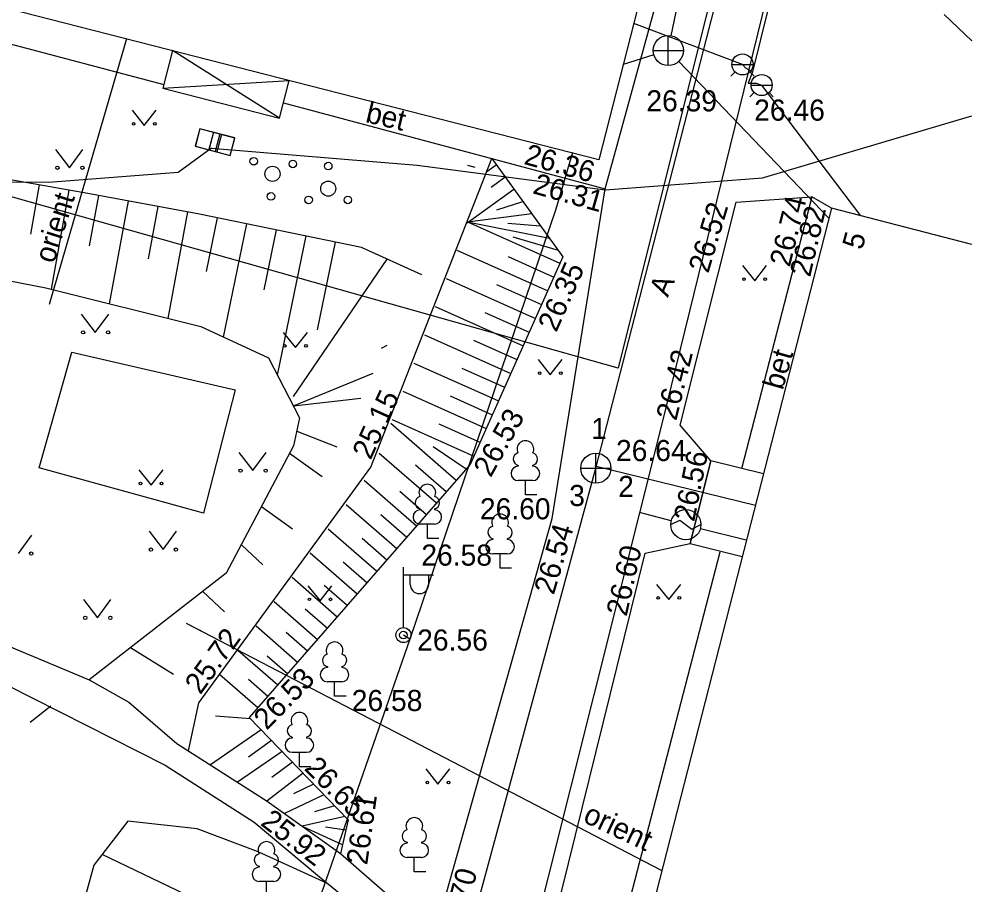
# Model space of a CAD drawing. Extents: x 714391 to 714584, y 6589993 to 6590151.
# Drawn here: x 714552.34 to 714583.92, y 6590039.38 to 6590068.08 of the extents above; entities that cross this region are included whole.
import ezdxf

# ---------------------------------------------------------------- set-up
doc = ezdxf.new("R2010")
doc.units = 0
for name, color, linetype in [('HALJASTUS', 7, 'Continuous'), ('HOONE', 7, 'Continuous'), ('HOONEDET', 7, 'Continuous'), ('KKAEV', 7, 'Continuous'), ('KORGUS', 7, 'Continuous'), ('KTRASS', 7, 'Continuous'), ('MPKAABEL', 7, 'Continuous'), ('POST', 7, 'Continuous'), ('PUU', 7, 'Continuous'), ('RAJATIS', 7, 'Continuous'), ('RELJEEF', 7, 'Continuous'), ('SITRASS', 7, 'Continuous'), ('SKTRASS', 7, 'Continuous'), ('TEE', 7, 'Continuous'), ('TORU NR', 7, 'Continuous'), ('VKAEV', 7, 'Continuous'), ('VTRASS', 7, 'Continuous'), ('Слой 1', 7, 'Continuous')]:
    doc.layers.add(name, color=color, linetype=linetype)

msp = doc.modelspace()

# ---------------------------------------------------------------- linework, layer by layer
at = {"layer": 'HALJASTUS'}
for p, q in [((714556.086, 6590065.052), (714556.491, 6590064.547)), ((714556.491, 6590064.547), (714556.886, 6590065.052)), ((714553.55, 6590063.754), (714554.013, 6590063.147)), ((714554.013, 6590063.147), (714554.459, 6590063.754)), ((714576.315, 6590059.904), (714576.72, 6590059.399)), ((714576.72, 6590059.399), (714577.115, 6590059.904)), ((714554.401, 6590058.3), (714554.864, 6590057.693)), ((714554.864, 6590057.693), (714555.31, 6590058.3)), ((714561.098, 6590057.692), (714561.503, 6590057.187)), ((714561.503, 6590057.187), (714561.898, 6590057.692)), ((714569.542, 6590056.789), (714569.947, 6590056.284)), ((714569.947, 6590056.284), (714570.342, 6590056.789)), ((714559.622, 6590053.715), (714560.085, 6590053.108)), ((714560.085, 6590053.108), (714560.531, 6590053.715)), ((714556.312, 6590053.131), (714556.717, 6590052.626)), ((714556.717, 6590052.626), (714557.112, 6590053.131)), ((714552.318, 6590050.359), (714552.764, 6590050.966)), ((714556.648, 6590051.099), (714557.111, 6590050.492)), ((714557.111, 6590050.492), (714557.557, 6590051.099)), ((714561.911, 6590049.293), (714562.316, 6590048.788)), ((714562.316, 6590048.788), (714562.711, 6590049.293)), ((714573.47, 6590049.338), (714573.875, 6590048.833)), ((714573.875, 6590048.833), (714574.27, 6590049.338)), ((714554.474, 6590048.837), (714554.937, 6590048.23)), ((714554.937, 6590048.23), (714555.383, 6590048.837)), ((714565.819, 6590043.22), (714566.224, 6590042.715)), ((714566.224, 6590042.715), (714566.619, 6590043.22))]:
    msp.add_line(p, q, dxfattribs=at)
for centre, radius in [((714556.138, 6590064.602), 0.0428), ((714556.838, 6590064.602), 0.0452), ((714553.612, 6590063.147), 0.055), ((714554.441, 6590063.147), 0.055), ((714576.367, 6590059.454), 0.0428), ((714577.067, 6590059.454), 0.0452), ((714554.463, 6590057.693), 0.055), ((714555.292, 6590057.693), 0.055), ((714561.15, 6590057.242), 0.0428), ((714561.85, 6590057.242), 0.0452), ((714569.594, 6590056.339), 0.0428), ((714570.294, 6590056.339), 0.0452), ((714559.684, 6590053.108), 0.055), ((714560.513, 6590053.108), 0.055), ((714556.364, 6590052.681), 0.0428), ((714557.064, 6590052.681), 0.0452), ((714552.746, 6590050.359), 0.055), ((714556.71, 6590050.492), 0.055), ((714557.539, 6590050.492), 0.055), ((714561.963, 6590048.843), 0.0428), ((714562.663, 6590048.843), 0.0452), ((714573.522, 6590048.889), 0.0428), ((714574.222, 6590048.889), 0.0452), ((714554.536, 6590048.23), 0.055), ((714555.365, 6590048.23), 0.055), ((714565.871, 6590042.77), 0.0428), ((714566.571, 6590042.77), 0.0452)]:
    msp.add_circle(centre, radius, dxfattribs=at)
at = {"layer": 'HOONE'}
for p, q in [((714573.956, 6590051.446), (714572.902, 6590051.725)), ((714573.939, 6590051.318), (714574.239, 6590051.468)), ((714574.239, 6590051.468), (714574.639, 6590051.168)), ((714574.639, 6590051.168), (714574.939, 6590051.318)), ((714574.924, 6590051.196), (714576.435, 6590050.818))]:
    msp.add_line(p, q, dxfattribs=at)
for points in [[(714571.553, 6590063.416), (714531.849, 6590073.579), (714534.607, 6590084.082)], [(714534.607, 6590084.082), (714574.255, 6590073.951), (714571.553, 6590063.416)], [(714564.262, 6590078.768), (714578.616, 6590074.926), (714573.649, 6590054.703), (714566.105, 6590024.628), (714563.31, 6590014.121), (714563.349, 6590014.272), (714562.951, 6590012.774), (714559.846, 6590001.436), (714579.323, 6589995.303), (714578.688, 6589992.711)], [(714557.429, 6590067.031), (714557.109, 6590065.783), (714560.975, 6590064.794), (714561.294, 6590066.042)], [(714583.92, 6590060.605), (714579.267, 6590061.805), (714569.151, 6590022.283), (714566.669, 6590012.701), (714564.179, 6590002.982), (714564.176, 6590002.972), (714574.684, 6590000.28), (714583.92, 6590036.33)], [(714577.009, 6590053.004), (714575.263, 6590053.437), (714574.585, 6590050.689), (714576.306, 6590050.266)]]:
    msp.add_lwpolyline(points, dxfattribs=at)
msp.add_circle((714574.439, 6590051.318), 0.5, dxfattribs=at)
at = {"layer": 'HOONEDET'}
for p, q in [((714560.975, 6590064.794), (714557.429, 6590067.031)), ((714557.109, 6590065.783), (714561.294, 6590066.042)), ((714574.585, 6590050.689), (714575.263, 6590053.437))]:
    msp.add_line(p, q, dxfattribs=at)
at = {"layer": 'KKAEV'}
for p, q in [((714573.858, 6590066.535), (714573.858, 6590067.535)), ((714573.358, 6590067.035), (714574.358, 6590067.035)), ((714571.457, 6590052.69), (714571.457, 6590053.69)), ((714570.957, 6590053.19), (714571.957, 6590053.19))]:
    msp.add_line(p, q, dxfattribs=at)
for centre in [(714573.858, 6590067.035), (714571.457, 6590053.19)]:
    msp.add_circle(centre, 0.5, dxfattribs=at)
at = {"layer": 'KTRASS'}
for p, q in [((714571.457, 6590053.19), (714577.77, 6590077.701)), ((714573.381, 6590066.887), (714572.362, 6590066.57)), ((714566.306, 6590034.202), (714571.457, 6590053.19)), ((714571.425, 6590053.27), (714576.748, 6590051.963))]:
    msp.add_line(p, q, dxfattribs=at)
at = {"layer": 'MPKAABEL'}
for points in [[(714558.719, 6590063.793), (714565.529, 6590063.23), (714571.775, 6590062.412), (714576.976, 6590062.818), (714583.92, 6590064.869)], [(714558.719, 6590063.793), (714557.614, 6590062.993), (714553.32, 6590062.662), (714527.694, 6590062.802), (714519.691, 6590062.433), (714508.979, 6590063.853), (714473.93, 6590041.599)], [(714570.681, 6590063.65), (714570.135, 6590061.772), (714565.296, 6590047.518), (714565.078, 6590047.659)], [(714565.296, 6590047.518), (714562.179, 6590038.578), (714559.533, 6590030.225), (714556.889, 6590017.808), (714556.781, 6590017.088), (714556.359, 6590014.294), (714555.801, 6590010.589), (714547.733, 6590015.896), (714531.176, 6590026.61), (714500.538, 6590019.577)]]:
    msp.add_lwpolyline(points, dxfattribs=at)
at = {"layer": 'POST'}
for p, q in [((714558.336, 6590064.443), (714558.181, 6590063.867)), ((714558.336, 6590064.443), (714558.182, 6590063.867)), ((714559.49, 6590064.136), (714558.336, 6590064.443)), ((714559.489, 6590064.133), (714558.336, 6590064.443)), ((714558.781, 6590064.323), (714558.626, 6590063.747)), ((714558.782, 6590064.325), (714558.628, 6590063.748)), ((714558.992, 6590064.269), (714558.838, 6590063.692)), ((714559.044, 6590064.253), (714558.889, 6590063.677)), ((714559.334, 6590063.557), (714559.489, 6590064.133)), ((714559.337, 6590063.559), (714559.49, 6590064.136)), ((714558.181, 6590063.867), (714559.334, 6590063.557)), ((714558.182, 6590063.867), (714559.337, 6590063.559)), ((714565.078, 6590047.909), (714565.078, 6590049.909)), ((714565.078, 6590049.659), (714566.078, 6590049.659)), ((714565.305, 6590049.338), (714565.305, 6590049.659)), ((714565.917, 6590049.338), (714565.917, 6590049.659)), ((714565.078, 6590047.659), (714565.078, 6590047.659))]:
    msp.add_line(p, q, dxfattribs=at)
for radius in [0.25, 0.127]:
    msp.add_circle((714565.078, 6590047.659), radius, dxfattribs=at)
msp.add_arc((714565.611, 6590049.338), 0.306, 180, 0, dxfattribs=at)
at = {"layer": 'PUU'}
for p, q in [((714568.881, 6590053.284), (714568.881, 6590053.254)), ((714569.361, 6590053.284), (714569.361, 6590053.254)), ((714569.361, 6590052.779), (714568.881, 6590052.779)), ((714569.121, 6590052.304), (714569.121, 6590052.779)), ((714569.501, 6590052.304), (714569.121, 6590052.304)), ((714565.631, 6590051.839), (714565.631, 6590051.809)), ((714566.111, 6590051.839), (714566.111, 6590051.809)), ((714566.111, 6590051.334), (714565.631, 6590051.334)), ((714565.871, 6590050.859), (714565.871, 6590051.334)), ((714566.251, 6590050.859), (714565.871, 6590050.859)), ((714568.042, 6590050.852), (714568.042, 6590050.822)), ((714568.522, 6590050.852), (714568.522, 6590050.822)), ((714568.522, 6590050.347), (714568.042, 6590050.347)), ((714568.282, 6590049.872), (714568.282, 6590050.347)), ((714568.662, 6590049.872), (714568.282, 6590049.872)), ((714562.557, 6590046.612), (714562.557, 6590046.582)), ((714563.037, 6590046.612), (714563.037, 6590046.582)), ((714563.037, 6590046.107), (714562.557, 6590046.107)), ((714562.797, 6590045.632), (714562.797, 6590046.107)), ((714563.177, 6590045.632), (714562.797, 6590045.632)), ((714561.391, 6590044.276), (714561.391, 6590044.246)), ((714561.871, 6590044.276), (714561.871, 6590044.246)), ((714561.871, 6590043.771), (714561.391, 6590043.771)), ((714561.631, 6590043.296), (714561.631, 6590043.771)), ((714562.011, 6590043.296), (714561.631, 6590043.296)), ((714565.2, 6590040.79), (714565.2, 6590040.76)), ((714565.68, 6590040.79), (714565.68, 6590040.76)), ((714565.68, 6590040.285), (714565.2, 6590040.285)), ((714565.44, 6590039.81), (714565.44, 6590040.285)), ((714560.299, 6590039.995), (714560.299, 6590039.965)), ((714560.779, 6590039.995), (714560.779, 6590039.965)), ((714565.82, 6590039.81), (714565.44, 6590039.81)), ((714560.779, 6590039.49), (714560.299, 6590039.49)), ((714560.539, 6590039.015), (714560.539, 6590039.49))]:
    msp.add_line(p, q, dxfattribs=at)
for centre, radius in [((714560.118, 6590063.365), 0.125), ((714561.414, 6590063.275), 0.125), ((714562.586, 6590063.206), 0.125), ((714560.74, 6590062.946), 0.25), ((714562.586, 6590062.456), 0.25), ((714560.688, 6590062.198), 0.125), ((714561.936, 6590062.081), 0.125), ((714563.236, 6590062.081), 0.125)]:
    msp.add_circle(centre, radius, dxfattribs=at)
for centre, radius, start, end in [((714569.121, 6590053.824), 0.277, 332.5799, 207.4201), ((714568.931, 6590053.491), 0.212, 105.2441, 257.079), ((714569.311, 6590053.491), 0.212, 282.921, 74.7559), ((714568.883, 6590053.016), 0.237, 90, 270), ((714569.358, 6590053.016), 0.237, 270, 90), ((714565.871, 6590052.379), 0.277, 332.5799, 207.4201), ((714565.681, 6590052.047), 0.212, 105.2441, 257.079), ((714566.061, 6590052.047), 0.212, 282.921, 74.7559), ((714565.633, 6590051.571), 0.237, 90, 270), ((714566.108, 6590051.571), 0.237, 270, 90), ((714568.282, 6590051.392), 0.277, 332.5799, 207.4201), ((714568.092, 6590051.06), 0.212, 105.2441, 257.079), ((714568.472, 6590051.06), 0.212, 282.921, 74.7559), ((714568.044, 6590050.585), 0.237, 90, 270), ((714568.519, 6590050.585), 0.237, 270, 90), ((714562.797, 6590047.152), 0.277, 332.5799, 207.4201), ((714562.607, 6590046.82), 0.212, 105.2441, 257.079), ((714562.987, 6590046.82), 0.212, 282.921, 74.7559), ((714562.559, 6590046.345), 0.237, 90, 270), ((714563.034, 6590046.345), 0.237, 270, 90), ((714561.631, 6590044.816), 0.277, 332.5799, 207.4201), ((714561.441, 6590044.484), 0.212, 105.2441, 257.079), ((714561.821, 6590044.484), 0.212, 282.921, 74.7559), ((714561.394, 6590044.009), 0.237, 90, 270), ((714561.869, 6590044.009), 0.237, 270, 90), ((714565.44, 6590041.33), 0.277, 332.5799, 207.4201), ((714565.25, 6590040.998), 0.212, 105.2441, 257.079), ((714565.63, 6590040.998), 0.212, 282.921, 74.7559), ((714560.539, 6590040.535), 0.277, 332.5799, 207.4201), ((714565.202, 6590040.522), 0.237, 90, 270), ((714565.677, 6590040.522), 0.237, 270, 90), ((714560.349, 6590040.203), 0.212, 105.2441, 257.079), ((714560.729, 6590040.203), 0.212, 282.921, 74.7559), ((714560.301, 6590039.728), 0.237, 90, 270), ((714560.776, 6590039.728), 0.237, 270, 90)]:
    msp.add_arc(centre, radius, start, end, dxfattribs=at)
at = {"layer": 'RAJATIS'}
msp.add_lwpolyline([(714553.005, 6590053.203), (714554.089, 6590057.037), (714559.498, 6590055.785), (714558.455, 6590051.694), (714553.005, 6590053.203)], dxfattribs=at)
at = {"layer": 'RELJEEF'}
for p, q in [((714583.913, 6590067.367), (714583.92, 6590067.381)), ((714567.847, 6590063.025), (714568.157, 6590063.249)), ((714567.986, 6590062.508), (714568.45, 6590062.843)), ((714567.195, 6590061.319), (714568.743, 6590062.438)), ((714568.178, 6590061.751), (714569.036, 6590062.033)), ((714567.207, 6590061.351), (714569.329, 6590061.628)), ((714567.207, 6590061.351), (714569.915, 6590060.817)), ((714567.207, 6590061.351), (714570.267, 6590059.983)), ((714568.537, 6590061.314), (714569.622, 6590061.223)), ((714568.705, 6590060.854), (714570.207, 6590060.412)), ((714566.85, 6590060.415), (714569.859, 6590059.07)), ((714568.546, 6590060.205), (714570.063, 6590059.526)), ((714566.492, 6590059.48), (714569.451, 6590058.157)), ((714568.163, 6590059.281), (714569.655, 6590058.614)), ((714566.134, 6590058.544), (714569.043, 6590057.244)), ((714567.78, 6590058.356), (714569.247, 6590057.701)), ((714565.776, 6590057.609), (714568.635, 6590056.331)), ((714567.397, 6590057.432), (714568.839, 6590056.788)), ((714565.419, 6590056.674), (714568.227, 6590055.418)), ((714567.014, 6590056.508), (714568.431, 6590055.875)), ((714565.061, 6590055.738), (714567.819, 6590054.505)), ((714566.631, 6590055.584), (714568.023, 6590054.962)), ((714564.703, 6590054.803), (714567.41, 6590053.592)), ((714564.658, 6590054.684), (714566.829, 6590052.79)), ((714566.248, 6590054.66), (714567.615, 6590054.049)), ((714566.061, 6590053.909), (714567.158, 6590053.167)), ((714564.277, 6590053.689), (714566.172, 6590052.037)), ((714565.484, 6590053.3), (714566.5, 6590052.413)), ((714563.78, 6590052.796), (714565.515, 6590051.283)), ((714564.961, 6590052.429), (714565.843, 6590051.66)), ((714563.182, 6590051.99), (714564.857, 6590050.529)), ((714564.334, 6590051.65), (714565.186, 6590050.906)), ((714562.585, 6590051.185), (714564.2, 6590049.776)), ((714563.706, 6590050.87), (714564.529, 6590050.153)), ((714561.987, 6590050.379), (714563.543, 6590049.022)), ((714563.078, 6590050.09), (714563.871, 6590049.399)), ((714561.389, 6590049.574), (714562.885, 6590048.268)), ((714562.451, 6590049.311), (714563.214, 6590048.645)), ((714560.791, 6590048.768), (714562.228, 6590047.515)), ((714561.823, 6590048.531), (714562.557, 6590047.892)), ((714560.193, 6590047.963), (714561.571, 6590046.761)), ((714561.196, 6590047.752), (714561.899, 6590047.138)), ((714559.596, 6590047.157), (714560.913, 6590046.008)), ((714560.568, 6590046.972), (714561.242, 6590046.384)), ((714558.998, 6590046.351), (714560.256, 6590045.254)), ((714559.941, 6590046.193), (714560.585, 6590045.631)), ((714560.015, 6590044.879), (714558.847, 6590044.976)), ((714560.362, 6590044.52), (714558.687, 6590043.352)), ((714560.71, 6590044.16), (714559.945, 6590043.609)), ((714561.057, 6590043.8), (714559.58, 6590042.782)), ((714561.404, 6590043.441), (714560.712, 6590042.937)), ((714561.752, 6590043.081), (714560.557, 6590042.158)), ((714562.099, 6590042.721), (714561.44, 6590042.394)), ((714562.446, 6590042.362), (714561.141, 6590041.739)), ((714562.794, 6590042.002), (714562.135, 6590041.794)), ((714563.141, 6590041.642), (714561.719, 6590041.325)), ((714563.056, 6590040.704), (714561.756, 6590041.298)), ((714563.166, 6590041.192), (714562.493, 6590041.296))]:
    msp.add_line(p, q, dxfattribs=at)
for points in [[(714565.692, 6590059.595), (714563.686, 6590060.51), (714558.32, 6590061.614), (714554.618, 6590062.293), (714548.983, 6590063.29), (714543.482, 6590064.178), (714539.992, 6590064.464), (714539.958, 6590064.473)], [(714557.95, 6590043.822), (714558.299, 6590045.41), (714564.001, 6590053.228), (714568.011, 6590063.451)], [(714568.011, 6590063.451), (714570.363, 6590060.197), (714567.286, 6590053.314), (714559.97, 6590044.926), (714563.243, 6590041.537), (714562.991, 6590040.414)], [(714552.725, 6590060.949), (714553.013, 6590062.577)], [(714553.417, 6590059.121), (714553.997, 6590062.403)], [(714539.606, 6590062.064), (714540.223, 6590061.953), (714543.767, 6590061.231), (714548.275, 6590060.13), (714553.23, 6590059.168), (714558.369, 6590057.882), (714560.606, 6590056.851), (714561.638, 6590054.857), (714561.432, 6590053.929), (714559.208, 6590049.705), (714554.662, 6590046.175)], [(714554.675, 6590060.555), (714554.982, 6590062.226)], [(714555.341, 6590058.64), (714555.965, 6590062.046)], [(714556.631, 6590060.131), (714556.949, 6590061.866)], [(714557.285, 6590058.154), (714557.932, 6590061.685)], [(714558.547, 6590059.711), (714558.914, 6590061.492)], [(714559.12, 6590057.536), (714559.893, 6590061.291)], [(714560.463, 6590059.097), (714560.872, 6590061.089)], [(714560.903, 6590056.277), (714561.852, 6590060.887)], [(714562.232, 6590057.776), (714562.831, 6590060.686)], [(714561.431, 6590055.566), (714564.541, 6590060.12)], [(714564.351, 6590057.165), (714564.537, 6590057.263)], [(714561.431, 6590055.258), (714564.08, 6590056.339)], [(714561.431, 6590055.258), (714563.671, 6590055.513)], [(714561.541, 6590054.419), (714562.87, 6590053.895)], [(714561.305, 6590053.689), (714562.386, 6590052.918)], [(714560.373, 6590051.919), (714561.403, 6590051.178)], [(714559.708, 6590050.655), (714560.421, 6590049.982)], [(714558.436, 6590049.105), (714559.149, 6590048.432)], [(714556.038, 6590047.243), (714557.454, 6590046.368)], [(714552.707, 6590044.773), (714553.389, 6590045.316)], [(714562.558, 6590039.424), (714560.262, 6590040.479), (714558.242, 6590041.236), (714555.943, 6590041.488), (714554.821, 6590040.031), (714554.512, 6590038.91), (714553.923, 6590035.744), (714553.979, 6590034.203), (714549.861, 6590019.341)]]:
    msp.add_lwpolyline(points, dxfattribs=at)
at = {"layer": 'SITRASS'}
for p, q in [((714555.896, 6590067.424), (714553.335, 6590058.614)), ((714573.627, 6590039.859), (714557.885, 6590048.045)), ((714558.548, 6590047.7), (714557.885, 6590048.045))]:
    msp.add_line(p, q, dxfattribs=at)
at = {"layer": 'SKTRASS'}
for p, q in [((714573.957, 6590067.525), (714579.488, 6590095.048)), ((714579.182, 6590061.474), (714574.204, 6590066.674))]:
    msp.add_line(p, q, dxfattribs=at)
at = {"layer": 'TEE'}
for p, q in [((714545.64, 6590068.929), (714557.142, 6590065.913)), ((714575.561, 6590050.401), (714571.262, 6590033.816))]:
    msp.add_line(p, q, dxfattribs=at)
for points in [[(714561.103, 6590065.296), (714571.762, 6590062.449), (714575.085, 6590074.574), (714565.709, 6590077.022)], [(714583.002, 6590068.223), (714583.92, 6590067.36)], [(714567.455, 6590063.157), (714567.214, 6590063.227)], [(714523.83, 6590060.323), (714524.838, 6590059.346), (714527.207, 6590057.322), (714530.612, 6590055.143), (714533.466, 6590053.803), (714539.862, 6590051.373), (714544.939, 6590049.949), (714549.327, 6590048.405), (714554.662, 6590046.175), (714555.973, 6590045.43), (714557.565, 6590044.068), (714560.558, 6590042.157), (714562.991, 6590040.414), (714566.112, 6590037.695), (714570.003, 6590051.519), (714571.762, 6590062.449)], [(714575.263, 6590053.437), (714574.251, 6590054.617), (714576.106, 6590062.004), (714578.616, 6590062.186)], [(714579.267, 6590061.805), (714578.616, 6590062.186), (714576.278, 6590053.167)], [(714530.594, 6590004.671), (714529.575, 6590005.355), (714533.957, 6590012.977), (714534.157, 6590015.322), (714534.216, 6590016.497), (714533.749, 6590019.201), (714531.843, 6590023.902), (714529.246, 6590029.211), (714527.989, 6590032.696), (714528.19, 6590034.745), (714530.462, 6590043.175), (714532.838, 6590052.177), (714538.719, 6590050.416), (714545.918, 6590048.286), (714551.944, 6590046.002), (714557.184, 6590043.351), (714560.131, 6590041.46), (714562.296, 6590039.644), (714565.486, 6590037.034), (714564.832, 6590036.22), (714560.292, 6590037.889), (714555.09, 6590040.381)], [(714570.266, 6590034.075), (714569.384, 6590035.393), (714573.093, 6590050.376), (714574.585, 6590050.689)]]:
    msp.add_lwpolyline(points, dxfattribs=at)
at = {"layer": 'VKAEV'}
for p, q in [((714575.965, 6590066.573), (714576.665, 6590066.573)), ((714576.068, 6590066.326), (714575.928, 6590066.186)), ((714576.562, 6590066.326), (714576.702, 6590066.186)), ((714576.6, 6590065.889), (714577.3, 6590065.889)), ((714576.703, 6590065.642), (714576.563, 6590065.502)), ((714577.197, 6590065.642), (714577.337, 6590065.502))]:
    msp.add_line(p, q, dxfattribs=at)
for centre in [(714576.315, 6590066.573), (714576.95, 6590065.889)]:
    msp.add_circle(centre, 0.35, dxfattribs=at)
at = {"layer": 'VTRASS'}
for p, q in [((714576.315, 6590066.573), (714572.711, 6590067.931)), ((714576.95, 6590065.889), (714580.232, 6590061.556))]:
    msp.add_line(p, q, dxfattribs=at)
for points in [[(714583.92, 6590101.451), (714582.627, 6590094.792), (714580.583, 6590085.094), (714578.759, 6590074.872), (714576.646, 6590066.323), (714576.499, 6590065.948), (714576.768, 6590065.956), (714576.95, 6590065.889)], [(714576.646, 6590066.323), (714576.427, 6590066.453), (714576.315, 6590066.573)]]:
    msp.add_lwpolyline(points, dxfattribs=at)
at = {"layer": 'Слой 1'}
msp.add_lwpolyline([(714579.84, 6590087.07), (714574.08, 6590064.07), (714572.19, 6590056.5), (714562.09, 6590059.36), (714527.28, 6590069.21), (714532.4, 6590086.95)], close=True, dxfattribs=at)

# ---------------------------------------------------------------- texts
at = {"layer": 'HOONE'}
msp.add_text('5', height=0.7, rotation=74.1483, dxfattribs=at).set_placement((714580.279, 6590060.397))
at = {"layer": 'HOONEDET'}
for rotation, p in [(346.6797, (714563.789, 6590064.667)), (74.1412, (714577.649, 6590055.754))]:
    msp.add_text('bet', height=0.7, rotation=rotation, dxfattribs=at).set_placement(p)
at = {"layer": 'KORGUS'}
for s, p in [('26.39', (714573.13, 6590065.017)), ('26.46', (714576.703, 6590064.709)), ('26.64', (714572.123, 6590053.426)), ('26.60', (714567.613, 6590051.495)), ('26.58', (714565.672, 6590049.96)), ('26.56', (714565.534, 6590047.144)), ('26.58', (714563.366, 6590045.14))]:
    msp.add_text(s, height=0.7, dxfattribs=at).set_placement(p)
for s, rotation, p in [('26.36', 344.4707, (714569.042, 6590063.279)), ('26.31', 344.2313, (714569.331, 6590062.308)), ('26.52', 73.393, (714575.182, 6590059.627)), ('26.74', 76.139, (714577.882, 6590059.833)), ('26.82', 76.8035, (714578.555, 6590059.5)), ('26.35', 66.1941, (714570.147, 6590057.671)), ('26.42', 76.2062, (714574.12, 6590054.738)), ('25.15', 65.6063, (714563.992, 6590053.436)), ('26.53', 60.8519, (714567.971, 6590052.856)), ('26.56', 78.5729, (714574.714, 6590051.392)), ('26.54', 73.4531, (714570.061, 6590048.967)), ('26.60', 77.4631, (714572.475, 6590048.253)), ('25.72', 54.0245, (714558.347, 6590045.659)), ('26.53', 45.6161, (714560.548, 6590044.48)), ('26.65', 314.831, (714561.76, 6590043.215)), ('26.61', 81.9268, (714563.876, 6590040.016)), ('25.92', 322.6665, (714560.309, 6590041.382)), ('26.70', 74.9315, (714566.928, 6590037.554))]:
    msp.add_text(s, height=0.7, rotation=rotation, dxfattribs=at).set_placement(p)
at = {"layer": 'SITRASS'}
for rotation, p in [(72.5029, (714553.493, 6590059.946)), (334.8723, (714570.993, 6590041.481))]:
    msp.add_text('orient', height=0.7, rotation=rotation, dxfattribs=at).set_placement(p)
at = {"layer": 'TEE'}
msp.add_text('A', height=0.7, rotation=67.1355, dxfattribs=at).set_placement((714573.842, 6590058.831))
at = {"layer": 'TORU NR'}
for s, p in [('1', (714571.299, 6590054.154)), ('2', (714572.195, 6590052.234)), ('3', (714570.573, 6590051.935))]:
    msp.add_text(s, height=0.7, dxfattribs=at).set_placement(p)

doc.saveas('drawing.dxf')
